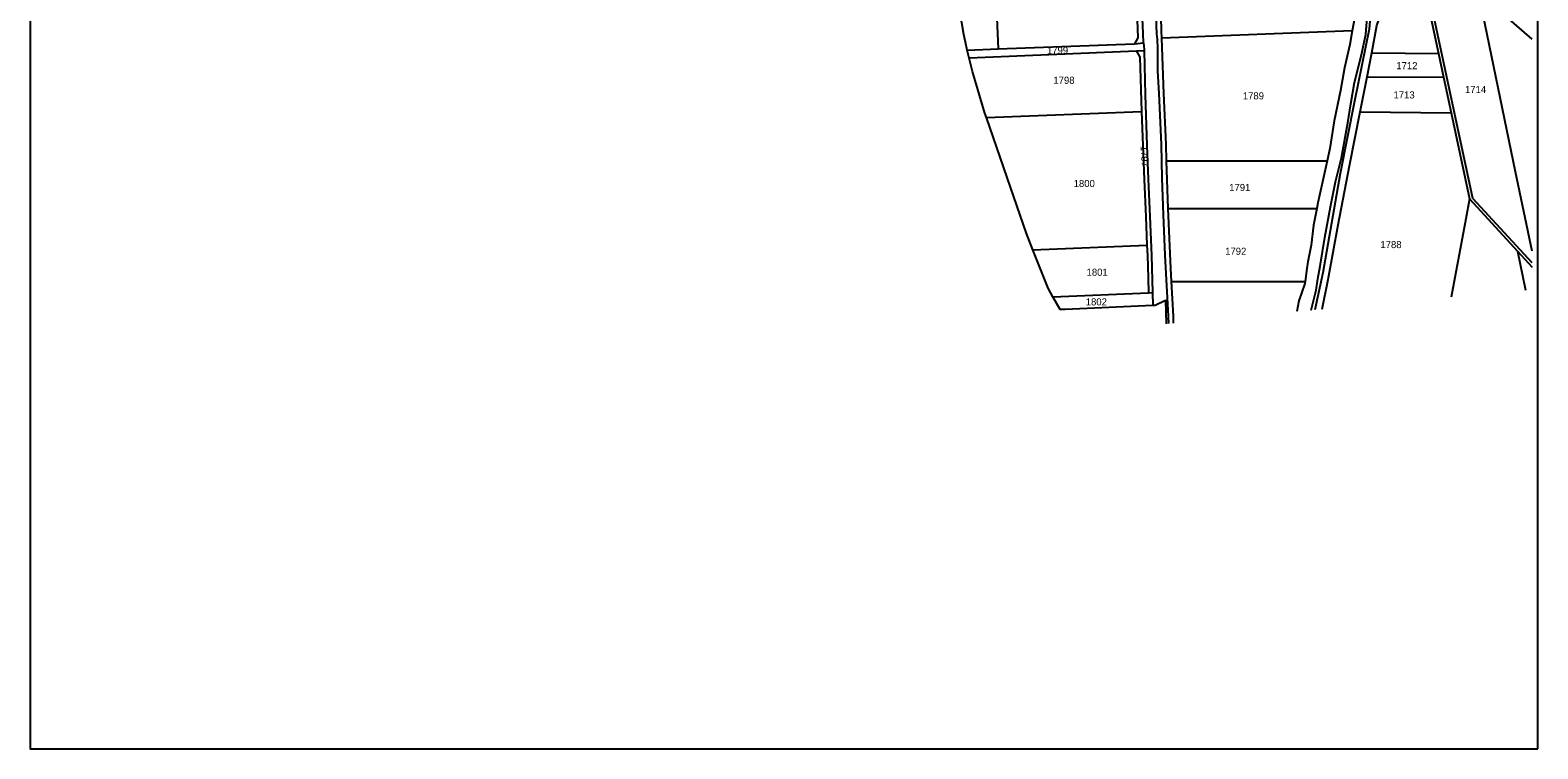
# Model space of a CAD drawing. Extents: x -584305 to -582773, y -1166873 to -1164754.
# Drawn here: x -584305 to -582820, y -1166873 to -1166166 of the extents above; entities that cross this region are included whole.
import ezdxf

# ---------------------------------------------------------------- set-up
doc = ezdxf.new("R2010")
doc.units = 0
for name, color, linetype in [('_Rám HC11-R', 7, 'Continuous'), ('Hranice parcel', 7, 'Continuous'), ('Parcelní čísla', 7, 'Continuous')]:
    doc.layers.add(name, color=color, linetype=linetype)

msp = doc.modelspace()

# ---------------------------------------------------------------- linework, layer by layer
at = {"layer": '_Rám HC11-R'}
msp.add_lwpolyline([(-582820, -1166873.1), (-582820, -1164773.1), (-584305, -1164773.1), (-584305, -1166873.1), (-582820, -1166873.1)], dxfattribs=at)
at = {"layer": 'Hranice parcel'}
for p, q in [((-583002.8, -1166166.4), (-583190.3, -1166173.7)), ((-583382, -1166185.3), (-583383.9, -1166177.6)), ((-583382, -1166185.3), (-583351.6, -1166184)), ((-583380.1, -1166193.3), (-583382, -1166185.3)), ((-583351.6, -1166184), (-583217.4, -1166179.2)), ((-583217.4, -1166179.2), (-583208.6, -1166178.2)), ((-583215.3, -1166186.6), (-583380.1, -1166193.3)), ((-583207.8, -1166186.2), (-583215.3, -1166186.6)), ((-582988.2, -1166211.6), (-582983.7, -1166188.2)), ((-582983.7, -1166188.2), (-582917.9, -1166188.7)), ((-582917.9, -1166188.7), (-582912.8, -1166212.2)), ((-582995.1, -1166246.2), (-582988.2, -1166211.6)), ((-582988.2, -1166211.6), (-582912.8, -1166212.2)), ((-582912.8, -1166212.2), (-582905.4, -1166247)), ((-583363.2, -1166251.9), (-583210.3, -1166245.7)), ((-582995.1, -1166246.2), (-582905.4, -1166247)), ((-582905.4, -1166247), (-582887.2, -1166331.9)), ((-583185.7, -1166294.4), (-583027.4, -1166294.4)), ((-583184.3, -1166341.3), (-583185.7, -1166294.4)), ((-582887.2, -1166331.9), (-582840.2, -1166383.3)), ((-583184.3, -1166341.3), (-583037.8, -1166341.3)), ((-583317.4, -1166381.9), (-583205, -1166377.3)), ((-582840.2, -1166383.3), (-582825.7, -1166399.1)), ((-583180.7, -1166413.2), (-583049.3, -1166413.2)), ((-583297.6, -1166428.1), (-583203.5, -1166424.2)), ((-583203.5, -1166424.2), (-583199.5, -1166424.1)), ((-583199.5, -1166424.1), (-583199.1, -1166436.8)), ((-583197.1, -1166436.7), (-583199.1, -1166436.8))]:
    msp.add_line(p, q, dxfattribs=at)
for points in [[(-583012.4, -1165748.2), (-583016.5, -1165758.9), (-583017, -1165788.4), (-583015.4, -1165822), (-583013.4, -1165843.2), (-583011.3, -1165864.4), (-582999.8, -1165958.9), (-582997.1, -1165981.8), (-582992.8, -1166018.3), (-582991.3, -1166032), (-582990, -1166050), (-582988.6, -1166068.1), (-582987.3, -1166081.4), (-582986, -1166094.7), (-582983.8, -1166135.7), (-582986.3, -1166164.8), (-583000.5, -1166235.8), (-583014.7, -1166306.9), (-583031.8, -1166404.6), (-583039.6, -1166441.1)], [(-583231.4, -1165901.9), (-583227.2, -1166006.9), (-583220.6, -1166009.4), (-583218.1, -1166066), (-583213.9, -1166173.2), (-583217.4, -1166179.2)], [(-583363.6, -1165907.4), (-583355.5, -1166093.1), (-583351.6, -1166184)], [(-582983.7, -1166188.2), (-582978.5, -1166161.2), (-582974.9, -1166151.1), (-582974.3, -1166130.6), (-582977.2, -1166120.6), (-582982.5, -1166063.2), (-582987.8, -1166005.9), (-582992.5, -1165964.7), (-582996.5, -1165931.9)], [(-582940.9, -1165931.9), (-582942.8, -1165992.4), (-582945, -1166061.9), (-582917.9, -1166188.7)], [(-583208.6, -1166178.2), (-583208.9, -1166169.2), (-583210.6, -1166124.8), (-583213.1, -1166072.8), (-583214, -1166035.8), (-583215.5, -1166006.5)], [(-583203.1, -1166002.3), (-583201.5, -1166034.7), (-583199.8, -1166073), (-583198.4, -1166093.9), (-583197.5, -1166118.9), (-583195.5, -1166169.3), (-583195.1, -1166174.6), (-583194.7, -1166183.8), (-583194.7, -1166188.4), (-583194.6, -1166205.8), (-583193.3, -1166228.2), (-583191.2, -1166278.2), (-583190.3, -1166311.3), (-583189.2, -1166347.4), (-583187.3, -1166387.1), (-583184, -1166447.4), (-583183.9, -1166454.5)], [(-582825.7, -1166394.7), (-582884, -1166331.4), (-582901.1, -1166251.7), (-582938.5, -1166076.9)], [(-583383.9, -1166177.6), (-583385.5, -1166169.9), (-583393.6, -1166121.9)], [(-583000.3, -1166124.4), (-582999.8, -1166134.5), (-583000.1, -1166141.9), (-583000.6, -1166154.3), (-583002.8, -1166166.4)], [(-583190.3, -1166173.7), (-583190.6, -1166166.4), (-583190.7, -1166163.7), (-583191.6, -1166139.1)], [(-582825.7, -1166383.4), (-582841.9, -1166305.3), (-582878.6, -1166128.5)], [(-582825.7, -1166174.6), (-582868.6, -1166137.1), (-582878.6, -1166128.5)], [(-583043.3, -1166441.5), (-583038.4, -1166421.8), (-583036.6, -1166410.6), (-583034.5, -1166398.2), (-583029.7, -1166369.9), (-583024.3, -1166339.7), (-583019.3, -1166314.9), (-583013.4, -1166291.3), (-583007.1, -1166257.1), (-583004.3, -1166238.2), (-583000.5, -1166217.2), (-582994.1, -1166191.4), (-582989.4, -1166169.9), (-582988.1, -1166153.2)], [(-583002.8, -1166166.4), (-583005.2, -1166179.8), (-583010.6, -1166202.7), (-583014.5, -1166225.2), (-583020.6, -1166255.1), (-583025, -1166282.2), (-583027.4, -1166294.4)], [(-583208.6, -1166178.2), (-583207.8, -1166184.7), (-583207.8, -1166186.2)], [(-583185.7, -1166294.4), (-583186.2, -1166278.1), (-583188.3, -1166228), (-583190.3, -1166173.7)], [(-583363.2, -1166251.9), (-583364.7, -1166247.4), (-583377, -1166206.4), (-583380.1, -1166193.3)], [(-583215.3, -1166186.6), (-583212.1, -1166192.5), (-583210.3, -1166245.7)], [(-583207.8, -1166186.2), (-583206.8, -1166229.5), (-583205.2, -1166279.2), (-583203.9, -1166312.5), (-583202.2, -1166349.2), (-583200.6, -1166387.4), (-583199.5, -1166424.1)], [(-583317.4, -1166381.9), (-583323.8, -1166365.9), (-583339.5, -1166320.2), (-583363.2, -1166251.9)], [(-583210.3, -1166245.7), (-583209.2, -1166279.3), (-583207.9, -1166312.7), (-583206.2, -1166349.4), (-583205, -1166377.3)], [(-583032.5, -1166440.5), (-583026.4, -1166411.2), (-583016.6, -1166357.3), (-583005.4, -1166299.2), (-582995.1, -1166246.2)], [(-583027.4, -1166294.4), (-583036.7, -1166335.7), (-583037.8, -1166341.3)], [(-582887.2, -1166331.9), (-582890.8, -1166351.4), (-582905.5, -1166428.7)], [(-583180.7, -1166413.2), (-583181.4, -1166400.5), (-583184.3, -1166341.3)], [(-583037.8, -1166341.3), (-583041.1, -1166357.6), (-583043.2, -1166377.5), (-583046.6, -1166393.7), (-583047.6, -1166400.5), (-583049.3, -1166413.2)], [(-583205, -1166377.3), (-583204.6, -1166387.6), (-583203.9, -1166409.7), (-583203.5, -1166424.2)], [(-583297.6, -1166428.1), (-583302.3, -1166419.6), (-583317.4, -1166381.9)], [(-582840.2, -1166383.3), (-582832.2, -1166421.8)], [(-583178.9, -1166454.1), (-583179, -1166447.4), (-583180.7, -1166413.2)], [(-583049.3, -1166413.2), (-583049.6, -1166415.2), (-583055.5, -1166432.2), (-583057.3, -1166442.8)], [(-583199.1, -1166436.8), (-583285.7, -1166440.6), (-583290.5, -1166440.7), (-583297.6, -1166428.1)], [(-583185.9, -1166454.7), (-583186.4, -1166431.8), (-583188.7, -1166432.9), (-583195, -1166435.7), (-583197.1, -1166436.7)]]:
    msp.add_lwpolyline(points, dxfattribs=at)

# ---------------------------------------------------------------- texts
at = {"layer": 'Parcelní čísla'}
for s, p in [('1799', (-583303.5, -1166189.2)), ('1712', (-582959.4, -1166204.2)), ('1798', (-583297.2, -1166218.6)), ('1789', (-583110.6, -1166233.9)), ('1713', (-582962.2, -1166233)), ('1714', (-582891.8, -1166227.7)), ('1800', (-583277.2, -1166320.2)), ('1791', (-583124, -1166324.1)), ('1788', (-582975.1, -1166380.3)), ('1792', (-583128, -1166386.9)), ('1801', (-583264.5, -1166407.5)), ('1802', (-583265.3, -1166436.7))]:
    msp.add_text(s, height=7, dxfattribs=at).set_placement(p)
msp.add_text('1797', height=7, rotation=273, dxfattribs=at).set_placement((-583211.3, -1166279.7))

doc.saveas('drawing.dxf')
